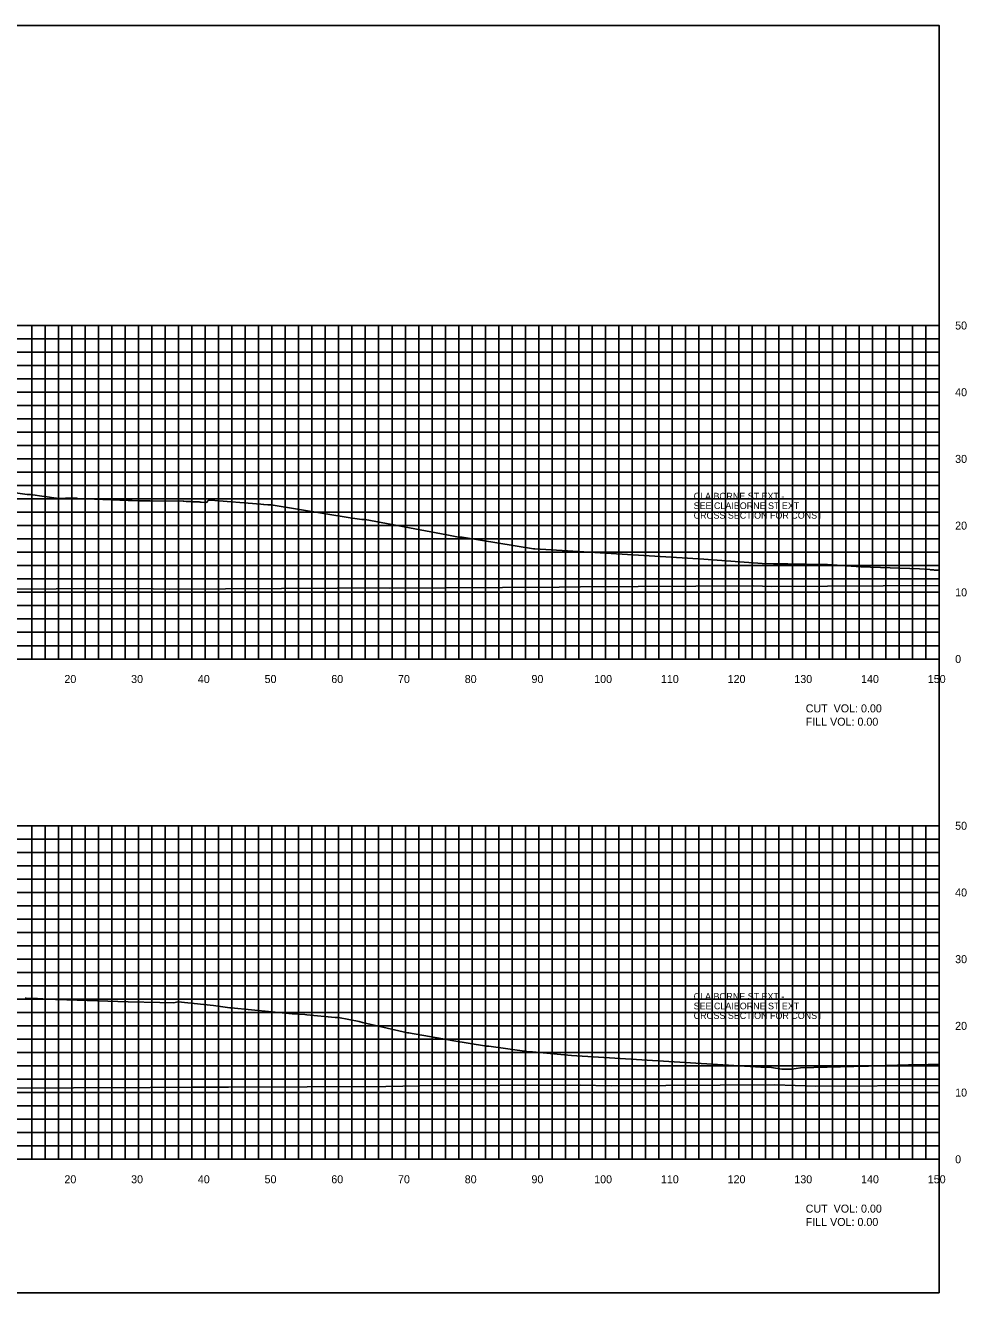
# Model space of a CAD drawing. Extents: x 1797305 to 1804485, y 245831 to 250849.
# Drawn here: x 1803664 to 1803805.1, y 250079.4 to 250269.4 of the extents above; entities that cross this region are included whole.
import ezdxf

# ---------------------------------------------------------------- set-up
doc = ezdxf.new("R2010")
doc.units = 0
for name, color, linetype in [('10', 7, 'Continuous'), ('29', 7, 'Continuous'), ('60', 7, 'Continuous'), ('CL-CNST', 7, 'Continuous'), ('EDPV-LINE', 7, 'Continuous'), ('Level 31', 7, 'Continuous'), ('LIMT-CSLINE', 7, 'Continuous'), ('M-ROADS', 7, 'Continuous')]:
    doc.layers.add(name, color=color, linetype=linetype)

msp = doc.modelspace()

# ---------------------------------------------------------------- linework, layer by layer
msp.add_lwpolyline([(1803501, 250079.43), (1803801, 250079.43), (1803801, 250269.43), (1803501, 250269.43)], close=True)
at = {"layer": '29'}
for p, q in [((1803501, 250224.43), (1803801, 250224.43)), ((1803665, 250174.43), (1803665, 250224.43)), ((1803667, 250174.43), (1803667, 250224.43)), ((1803669, 250174.43), (1803669, 250224.43)), ((1803671, 250174.43), (1803671, 250224.43)), ((1803673, 250174.43), (1803673, 250224.43)), ((1803675, 250174.43), (1803675, 250224.43)), ((1803677, 250174.43), (1803677, 250224.43)), ((1803679, 250174.43), (1803679, 250224.43)), ((1803681, 250174.43), (1803681, 250224.43)), ((1803683, 250174.43), (1803683, 250224.43)), ((1803685, 250174.43), (1803685, 250224.43)), ((1803687, 250174.43), (1803687, 250224.43)), ((1803689, 250174.43), (1803689, 250224.43)), ((1803691, 250174.43), (1803691, 250224.43)), ((1803693, 250174.43), (1803693, 250224.43)), ((1803695, 250174.43), (1803695, 250224.43)), ((1803697, 250174.43), (1803697, 250224.43)), ((1803699, 250174.43), (1803699, 250224.43)), ((1803701, 250174.43), (1803701, 250224.43)), ((1803703, 250174.43), (1803703, 250224.43)), ((1803705, 250174.43), (1803705, 250224.43)), ((1803707, 250174.43), (1803707, 250224.43)), ((1803709, 250174.43), (1803709, 250224.43)), ((1803711, 250174.43), (1803711, 250224.43)), ((1803713, 250174.43), (1803713, 250224.43)), ((1803715, 250174.43), (1803715, 250224.43)), ((1803717, 250174.43), (1803717, 250224.43)), ((1803719, 250174.43), (1803719, 250224.43)), ((1803721, 250174.43), (1803721, 250224.43)), ((1803723, 250174.43), (1803723, 250224.43)), ((1803725, 250174.43), (1803725, 250224.43)), ((1803727, 250174.43), (1803727, 250224.43)), ((1803729, 250174.43), (1803729, 250224.43)), ((1803731, 250174.43), (1803731, 250224.43)), ((1803733, 250174.43), (1803733, 250224.43)), ((1803735, 250174.43), (1803735, 250224.43)), ((1803737, 250174.43), (1803737, 250224.43)), ((1803739, 250174.43), (1803739, 250224.43)), ((1803741, 250174.43), (1803741, 250224.43)), ((1803743, 250174.43), (1803743, 250224.43)), ((1803745, 250174.43), (1803745, 250224.43)), ((1803747, 250174.43), (1803747, 250224.43)), ((1803749, 250174.43), (1803749, 250224.43)), ((1803751, 250174.43), (1803751, 250224.43)), ((1803753, 250174.43), (1803753, 250224.43)), ((1803755, 250174.43), (1803755, 250224.43)), ((1803757, 250174.43), (1803757, 250224.43)), ((1803759, 250174.43), (1803759, 250224.43)), ((1803761, 250174.43), (1803761, 250224.43)), ((1803763, 250174.43), (1803763, 250224.43)), ((1803765, 250174.43), (1803765, 250224.43)), ((1803767, 250174.43), (1803767, 250224.43)), ((1803769, 250174.43), (1803769, 250224.43)), ((1803771, 250174.43), (1803771, 250224.43)), ((1803773, 250174.43), (1803773, 250224.43)), ((1803775, 250174.43), (1803775, 250224.43)), ((1803777, 250174.43), (1803777, 250224.43)), ((1803779, 250174.43), (1803779, 250224.43)), ((1803781, 250174.43), (1803781, 250224.43)), ((1803783, 250174.43), (1803783, 250224.43)), ((1803785, 250174.43), (1803785, 250224.43)), ((1803787, 250174.43), (1803787, 250224.43)), ((1803789, 250174.43), (1803789, 250224.43)), ((1803791, 250174.43), (1803791, 250224.43)), ((1803793, 250174.43), (1803793, 250224.43)), ((1803795, 250174.43), (1803795, 250224.43)), ((1803797, 250174.43), (1803797, 250224.43)), ((1803799, 250174.43), (1803799, 250224.43)), ((1803801, 250174.43), (1803801, 250224.43)), ((1803501, 250222.43), (1803801, 250222.43)), ((1803501, 250220.43), (1803801, 250220.43)), ((1803501, 250218.43), (1803801, 250218.43)), ((1803501, 250216.43), (1803801, 250216.43)), ((1803501, 250214.43), (1803801, 250214.43)), ((1803501, 250212.43), (1803801, 250212.43)), ((1803501, 250210.43), (1803801, 250210.43)), ((1803501, 250208.43), (1803801, 250208.43)), ((1803501, 250206.43), (1803801, 250206.43)), ((1803501, 250204.43), (1803801, 250204.43)), ((1803501, 250202.43), (1803801, 250202.43)), ((1803501, 250200.43), (1803801, 250200.43)), ((1803501, 250198.43), (1803801, 250198.43)), ((1803501, 250196.43), (1803801, 250196.43)), ((1803501, 250194.43), (1803801, 250194.43)), ((1803501, 250192.43), (1803801, 250192.43)), ((1803501, 250190.43), (1803801, 250190.43)), ((1803501, 250188.43), (1803801, 250188.43)), ((1803501, 250186.43), (1803801, 250186.43)), ((1803501, 250184.43), (1803801, 250184.43)), ((1803501, 250182.43), (1803801, 250182.43)), ((1803501, 250180.43), (1803801, 250180.43)), ((1803501, 250178.43), (1803801, 250178.43)), ((1803501, 250176.43), (1803801, 250176.43)), ((1803501, 250174.43), (1803801, 250174.43)), ((1803501, 250149.43), (1803801, 250149.43)), ((1803665, 250099.43), (1803665, 250149.43)), ((1803667, 250099.43), (1803667, 250149.43)), ((1803669, 250099.43), (1803669, 250149.43)), ((1803671, 250099.43), (1803671, 250149.43)), ((1803673, 250099.43), (1803673, 250149.43)), ((1803675, 250099.43), (1803675, 250149.43)), ((1803677, 250099.43), (1803677, 250149.43)), ((1803679, 250099.43), (1803679, 250149.43)), ((1803681, 250099.43), (1803681, 250149.43)), ((1803683, 250099.43), (1803683, 250149.43)), ((1803685, 250099.43), (1803685, 250149.43)), ((1803687, 250099.43), (1803687, 250149.43)), ((1803689, 250099.43), (1803689, 250149.43)), ((1803691, 250099.43), (1803691, 250149.43)), ((1803693, 250099.43), (1803693, 250149.43)), ((1803695, 250099.43), (1803695, 250149.43)), ((1803697, 250099.43), (1803697, 250149.43)), ((1803699, 250099.43), (1803699, 250149.43)), ((1803701, 250099.43), (1803701, 250149.43)), ((1803703, 250099.43), (1803703, 250149.43)), ((1803705, 250099.43), (1803705, 250149.43)), ((1803707, 250099.43), (1803707, 250149.43)), ((1803709, 250099.43), (1803709, 250149.43)), ((1803711, 250099.43), (1803711, 250149.43)), ((1803713, 250099.43), (1803713, 250149.43)), ((1803715, 250099.43), (1803715, 250149.43)), ((1803717, 250099.43), (1803717, 250149.43)), ((1803719, 250099.43), (1803719, 250149.43)), ((1803721, 250099.43), (1803721, 250149.43)), ((1803723, 250099.43), (1803723, 250149.43)), ((1803725, 250099.43), (1803725, 250149.43)), ((1803727, 250099.43), (1803727, 250149.43)), ((1803729, 250099.43), (1803729, 250149.43)), ((1803731, 250099.43), (1803731, 250149.43)), ((1803733, 250099.43), (1803733, 250149.43)), ((1803735, 250099.43), (1803735, 250149.43)), ((1803737, 250099.43), (1803737, 250149.43)), ((1803739, 250099.43), (1803739, 250149.43)), ((1803741, 250099.43), (1803741, 250149.43)), ((1803743, 250099.43), (1803743, 250149.43)), ((1803745, 250099.43), (1803745, 250149.43)), ((1803747, 250099.43), (1803747, 250149.43)), ((1803749, 250099.43), (1803749, 250149.43)), ((1803751, 250099.43), (1803751, 250149.43)), ((1803753, 250099.43), (1803753, 250149.43)), ((1803755, 250099.43), (1803755, 250149.43)), ((1803757, 250099.43), (1803757, 250149.43)), ((1803759, 250099.43), (1803759, 250149.43)), ((1803761, 250099.43), (1803761, 250149.43)), ((1803763, 250099.43), (1803763, 250149.43)), ((1803765, 250099.43), (1803765, 250149.43)), ((1803767, 250099.43), (1803767, 250149.43)), ((1803769, 250099.43), (1803769, 250149.43)), ((1803771, 250099.43), (1803771, 250149.43)), ((1803773, 250099.43), (1803773, 250149.43)), ((1803775, 250099.43), (1803775, 250149.43)), ((1803777, 250099.43), (1803777, 250149.43)), ((1803779, 250099.43), (1803779, 250149.43)), ((1803781, 250099.43), (1803781, 250149.43)), ((1803783, 250099.43), (1803783, 250149.43)), ((1803785, 250099.43), (1803785, 250149.43)), ((1803787, 250099.43), (1803787, 250149.43)), ((1803789, 250099.43), (1803789, 250149.43)), ((1803791, 250099.43), (1803791, 250149.43)), ((1803793, 250099.43), (1803793, 250149.43)), ((1803795, 250099.43), (1803795, 250149.43)), ((1803797, 250099.43), (1803797, 250149.43)), ((1803799, 250099.43), (1803799, 250149.43)), ((1803801, 250099.43), (1803801, 250149.43)), ((1803501, 250147.43), (1803801, 250147.43)), ((1803501, 250145.43), (1803801, 250145.43)), ((1803501, 250143.43), (1803801, 250143.43)), ((1803501, 250141.43), (1803801, 250141.43)), ((1803501, 250139.43), (1803801, 250139.43)), ((1803501, 250137.43), (1803801, 250137.43)), ((1803501, 250135.43), (1803801, 250135.43)), ((1803501, 250133.43), (1803801, 250133.43)), ((1803501, 250131.43), (1803801, 250131.43)), ((1803501, 250129.43), (1803801, 250129.43)), ((1803501, 250127.43), (1803801, 250127.43)), ((1803501, 250125.43), (1803801, 250125.43)), ((1803501, 250123.43), (1803801, 250123.43)), ((1803501, 250121.43), (1803801, 250121.43)), ((1803501, 250119.43), (1803801, 250119.43)), ((1803501, 250117.43), (1803801, 250117.43)), ((1803501, 250115.43), (1803801, 250115.43)), ((1803501, 250113.43), (1803801, 250113.43)), ((1803501, 250111.43), (1803801, 250111.43)), ((1803501, 250109.43), (1803801, 250109.43)), ((1803501, 250107.43), (1803801, 250107.43)), ((1803501, 250105.43), (1803801, 250105.43)), ((1803501, 250103.43), (1803801, 250103.43)), ((1803501, 250101.43), (1803801, 250101.43)), ((1803501, 250099.43), (1803801, 250099.43))]:
    msp.add_line(p, q, dxfattribs=at)
at = {"layer": 'CL-CNST'}
for points in [[(1803501, 250185.09), (1803510.77, 250185), (1803527.31, 250184.97), (1803539.92, 250184.88), (1803558.56, 250184.87), (1803569.08, 250184.79), (1803589.45, 250184.81), (1803598.24, 250184.75), (1803620.07, 250184.81), (1803627.4, 250184.78), (1803650.47, 250184.88), (1803656.56, 250184.88), (1803680.69, 250185), (1803685.72, 250184.91), (1803710.78, 250185.05), (1803714.88, 250185.09), (1803718.62, 250185.06), (1803744.03, 250185.2), (1803747.27, 250185.25), (1803773.19, 250185.39), (1803775.9, 250185.32), (1803801, 250185.47)], [(1803501, 250110.24), (1803513.94, 250110.15), (1803529.55, 250110.14), (1803543.1, 250110.05), (1803560.71, 250110.06), (1803572.25, 250109.98), (1803591.54, 250110.03), (1803601.41, 250110), (1803622.13, 250110.08), (1803630.57, 250110.09), (1803652.52, 250110.19), (1803659.73, 250110.07), (1803682.75, 250110.19), (1803688.89, 250110.26), (1803694.5, 250110.22), (1803718.05, 250110.35), (1803723.18, 250110.43), (1803747.21, 250110.56), (1803751.83, 250110.43), (1803776.36, 250110.58), (1803782.45, 250110.38), (1803801, 250110.51)]]:
    msp.add_lwpolyline(points, dxfattribs=at)
at = {"layer": 'Level 31'}
for p, q in [((1803801, 250174.43), (1803801, 250224.43)), ((1803801.06, 250224.43), (1803801, 250224.43)), ((1803801.06, 250214.43), (1803801, 250214.43)), ((1803801.06, 250204.43), (1803801, 250204.43)), ((1803801.06, 250194.43), (1803801, 250194.43)), ((1803801.06, 250184.43), (1803801, 250184.43)), ((1803501, 250174.43), (1803801, 250174.43)), ((1803671, 250174.37), (1803671, 250174.43)), ((1803681, 250174.37), (1803681, 250174.43)), ((1803691, 250174.37), (1803691, 250174.43)), ((1803701, 250174.37), (1803701, 250174.43)), ((1803711, 250174.37), (1803711, 250174.43)), ((1803721, 250174.37), (1803721, 250174.43)), ((1803731, 250174.37), (1803731, 250174.43)), ((1803741, 250174.37), (1803741, 250174.43)), ((1803751, 250174.37), (1803751, 250174.43)), ((1803761, 250174.37), (1803761, 250174.43)), ((1803771, 250174.37), (1803771, 250174.43)), ((1803781, 250174.37), (1803781, 250174.43)), ((1803791, 250174.37), (1803791, 250174.43)), ((1803801, 250174.37), (1803801, 250174.43)), ((1803801.06, 250174.43), (1803801, 250174.43)), ((1803801, 250099.43), (1803801, 250149.43)), ((1803801.06, 250149.43), (1803801, 250149.43)), ((1803801.06, 250139.43), (1803801, 250139.43)), ((1803801.06, 250129.43), (1803801, 250129.43)), ((1803801.06, 250119.43), (1803801, 250119.43)), ((1803801.06, 250109.43), (1803801, 250109.43)), ((1803501, 250099.43), (1803801, 250099.43)), ((1803671, 250099.37), (1803671, 250099.43)), ((1803681, 250099.37), (1803681, 250099.43)), ((1803691, 250099.37), (1803691, 250099.43)), ((1803701, 250099.37), (1803701, 250099.43)), ((1803711, 250099.37), (1803711, 250099.43)), ((1803721, 250099.37), (1803721, 250099.43)), ((1803731, 250099.37), (1803731, 250099.43)), ((1803741, 250099.37), (1803741, 250099.43)), ((1803751, 250099.37), (1803751, 250099.43)), ((1803761, 250099.37), (1803761, 250099.43)), ((1803771, 250099.37), (1803771, 250099.43)), ((1803781, 250099.37), (1803781, 250099.43)), ((1803791, 250099.37), (1803791, 250099.43)), ((1803801, 250099.37), (1803801, 250099.43)), ((1803801.06, 250099.43), (1803801, 250099.43))]:
    msp.add_line(p, q, dxfattribs=at)
at = {"layer": 'M-ROADS'}
for points in [[(1803654.08, 250200.52), (1803664.32, 250199.09), (1803664.64, 250199.09), (1803664.82, 250199.09), (1803666.88, 250198.81), (1803666.97, 250198.81), (1803668.69, 250198.52), (1803668.71, 250198.52), (1803668.73, 250198.51), (1803668.74, 250198.51), (1803668.76, 250198.51), (1803668.77, 250198.51), (1803668.79, 250198.51), (1803668.8, 250198.51), (1803668.81, 250198.51), (1803668.82, 250198.51), (1803668.83, 250198.51), (1803668.84, 250198.51), (1803670.05, 250198.52), (1803670.14, 250198.52), (1803670.25, 250198.52), (1803670.37, 250198.52), (1803670.51, 250198.52), (1803670.68, 250198.53), (1803670.88, 250198.53), (1803671.13, 250198.53), (1803671.44, 250198.53), (1803671.76, 250198.54), (1803671.77, 250198.53), (1803671.81, 250198.52), (1803671.83, 250198.51), (1803671.85, 250198.51), (1803671.86, 250198.5), (1803671.87, 250198.5), (1803671.88, 250198.5), (1803679.48, 250198.2), (1803680.07, 250198.18), (1803681.07, 250198.16), (1803681.22, 250198.16), (1803681.7, 250198.16), (1803681.97, 250198.15), (1803682.75, 250198.14), (1803687.7, 250198.09), (1803687.78, 250198.09), (1803688.16, 250198.07), (1803688.47, 250198.05), (1803688.74, 250198.04), (1803688.96, 250198.03), (1803689.16, 250198.02), (1803689.33, 250198.02), (1803689.49, 250198.01), (1803689.62, 250198), (1803689.74, 250198), (1803689.85, 250197.99), (1803689.95, 250197.99), (1803690.04, 250197.98), (1803690.12, 250197.98), (1803690.15, 250197.98), (1803690.19, 250197.97), (1803690.25, 250197.97), (1803690.3, 250197.97), (1803690.35, 250197.96), (1803690.39, 250197.96), (1803691.2, 250197.9), (1803691.47, 250198.2), (1803691.76, 250198.23), (1803691.79, 250198.23), (1803699.32, 250197.64), (1803699.75, 250197.61), (1803699.78, 250197.61), (1803700.4, 250197.55), (1803700.88, 250197.54), (1803700.9, 250197.54), (1803712.75, 250195.62), (1803714.48, 250195.34), (1803714.93, 250195.34), (1803714.99, 250195.33), (1803727.22, 250193.04), (1803728.99, 250192.72), (1803729.45, 250192.72), (1803729.5, 250192.72), (1803740.2, 250190.96), (1803740.43, 250190.96), (1803765.72, 250189.4), (1803774.47, 250188.75), (1803776.18, 250188.72), (1803777.98, 250188.68), (1803778.34, 250188.68), (1803783.77, 250188.61), (1803783.95, 250188.61), (1803784.26, 250188.61), (1803789.28, 250188.25), (1803798.04, 250187.94), (1803799.6, 250187.84), (1803799.65, 250187.82), (1803799.87, 250187.82), (1803799.95, 250187.82), (1803800.16, 250187.82), (1803800.32, 250187.77), (1803801, 250187.75)], [(1803664, 250123.56), (1803664.08, 250123.56), (1803664.15, 250123.56), (1803664.21, 250123.55), (1803664.28, 250123.55), (1803664.34, 250123.55), (1803664.39, 250123.54), (1803664.44, 250123.54), (1803664.49, 250123.54), (1803664.54, 250123.53), (1803664.59, 250123.53), (1803664.6, 250123.53), (1803665.88, 250123.54), (1803667.54, 250123.42), (1803667.56, 250123.41), (1803668.59, 250123.38), (1803668.62, 250123.38), (1803670.26, 250123.34), (1803679.47, 250123.03), (1803684.22, 250122.95), (1803686.28, 250122.88), (1803686.89, 250123.03), (1803686.95, 250123.03), (1803692.27, 250122.49), (1803694.71, 250122.15), (1803694.91, 250122.15), (1803704.06, 250121.25), (1803705.94, 250121.12), (1803706.21, 250121.09), (1803710.47, 250120.67), (1803710.54, 250120.67), (1803710.97, 250120.67), (1803714.07, 250120.06), (1803714.22, 250120.02), (1803714.6, 250119.95), (1803721.31, 250118.39), (1803721.48, 250118.39), (1803727.76, 250117.27), (1803727.95, 250117.26), (1803733.17, 250116.38), (1803733.5, 250116.39), (1803739.57, 250115.56), (1803739.75, 250115.56), (1803740.08, 250115.56), (1803745.91, 250115.01), (1803774.28, 250113.26), (1803775.87, 250113.18), (1803777.41, 250112.96), (1803778.92, 250112.96), (1803780.24, 250113.13), (1803788.2, 250113.34), (1803790.4, 250113.39), (1803790.99, 250113.43), (1803791.42, 250113.43), (1803796.42, 250113.58), (1803796.88, 250113.59), (1803797.72, 250113.6), (1803801, 250113.7)]]:
    msp.add_lwpolyline(points, dxfattribs=at)

# ---------------------------------------------------------------- texts
at = {"layer": '10'}
for s, p in [('20', (1803669.9, 250170.83)), ('30', (1803679.9, 250170.83)), ('40', (1803689.9, 250170.83)), ('50', (1803699.9, 250170.83)), ('60', (1803709.9, 250170.83)), ('70', (1803719.9, 250170.83)), ('80', (1803729.9, 250170.83)), ('90', (1803739.9, 250170.83)), ('100', (1803749.3, 250170.83)), ('110', (1803759.3, 250170.83)), ('120', (1803769.3, 250170.83)), ('130', (1803779.3, 250170.83)), ('140', (1803789.3, 250170.83)), ('150', (1803799.3, 250170.83)), ('20', (1803669.9, 250095.83)), ('30', (1803679.9, 250095.83)), ('40', (1803689.9, 250095.83)), ('50', (1803699.9, 250095.83)), ('60', (1803709.9, 250095.83)), ('70', (1803719.9, 250095.83)), ('80', (1803729.9, 250095.83)), ('90', (1803739.9, 250095.83)), ('100', (1803749.3, 250095.83)), ('110', (1803759.3, 250095.83)), ('120', (1803769.3, 250095.83)), ('130', (1803779.3, 250095.83)), ('140', (1803789.3, 250095.83)), ('150', (1803799.3, 250095.83))]:
    msp.add_text(s, height=1.2, dxfattribs=at).set_placement(p)
at = {"layer": '60'}
for s, p in [('50', (1803803.4, 250223.83)), ('40', (1803803.4, 250213.83)), ('30', (1803803.4, 250203.83)), ('20', (1803803.4, 250193.83)), ('10', (1803803.4, 250183.83)), ('0', (1803803.4, 250173.83)), ('50', (1803803.4, 250148.83)), ('40', (1803803.4, 250138.83)), ('30', (1803803.4, 250128.83)), ('20', (1803803.4, 250118.83)), ('10', (1803803.4, 250108.83)), ('0', (1803803.4, 250098.83))]:
    msp.add_text(s, height=1.2, dxfattribs=at).set_placement(p)
at = {"layer": 'EDPV-LINE'}
for s, p in [('CUT  VOL: 0.00', (1803781, 250166.43)), ('FILL VOL: 0.00', (1803781, 250164.43)), ('CUT  VOL: 0.00', (1803781, 250091.43)), ('FILL VOL: 0.00', (1803781, 250089.43))]:
    msp.add_text(s, height=1.2, dxfattribs=at).set_placement(p)
at = {"layer": 'LIMT-CSLINE'}
for s, p in [('CLAIBORNE ST EXT -', (1803764.21, 250198.35)), ('SEE CLAIBORNE ST EXT', (1803764.21, 250196.91)), ('CROSS SECTION FOR CONST ', (1803764.21, 250195.47)), ('CLAIBORNE ST EXT -', (1803764.21, 250123.35)), ('SEE CLAIBORNE ST EXT', (1803764.21, 250121.91)), ('CROSS SECTION FOR CONST ', (1803764.21, 250120.47))]:
    msp.add_text(s, height=1, dxfattribs=at).set_placement(p)

doc.saveas('drawing.dxf')
